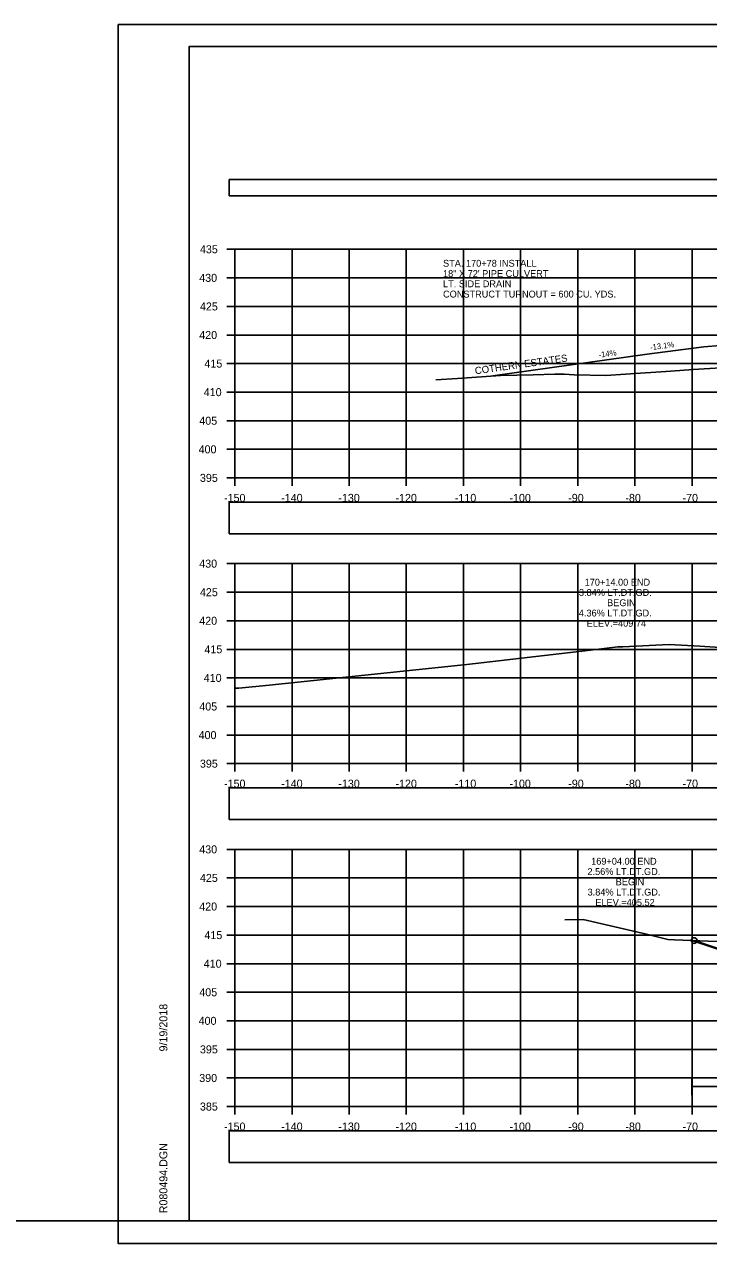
# Model space of a CAD drawing. Extents: x 1376273 to 1384221, y 378927 to 384592.
# Drawn here: x 1378403.8 to 1378523.5, y 381178.5 to 381391.9 of the extents above; entities that cross this region are included whole.
import ezdxf

# ---------------------------------------------------------------- set-up
doc = ezdxf.new("R2010")
doc.units = 0
for name, color, linetype in [('R_Axis', 7, 'Continuous'), ('R_Axis Annot', 7, 'Continuous'), ('R_Border', 7, 'Continuous'), ('R_Dimension', 7, 'Continuous'), ('R_Drive', 7, 'Continuous'), ('R_Exist Surface', 7, 'Continuous'), ('R_Fin Surface', 7, 'Continuous'), ('R_Grid', 7, 'Continuous'), ('R_No Plot', 7, 'Continuous'), ('R_Xsect Elev', 7, 'Continuous'), ('T_Detection Zones', 7, 'Continuous'), ('T_Drafting', 7, 'Continuous')]:
    doc.layers.add(name, color=color, linetype=linetype)

msp = doc.modelspace()

# ---------------------------------------------------------------- linework, layer by layer
at = {"layer": 'R_Axis'}
for p, q in [((1378439.24, 381352.51), (1378440.64, 381352.51)), ((1378440.64, 381312.51), (1378440.64, 381352.51)), ((1378439.24, 381347.51), (1378440.64, 381347.51)), ((1378439.24, 381342.51), (1378440.64, 381342.51)), ((1378439.24, 381337.51), (1378440.64, 381337.51)), ((1378439.24, 381332.51), (1378440.64, 381332.51)), ((1378439.24, 381327.51), (1378440.64, 381327.51)), ((1378439.24, 381322.51), (1378440.64, 381322.51)), ((1378439.24, 381317.51), (1378440.64, 381317.51)), ((1378439.24, 381312.51), (1378440.64, 381312.51)), ((1378440.64, 381312.51), (1378740.64, 381312.51)), ((1378440.64, 381311.11), (1378440.64, 381312.51)), ((1378450.64, 381311.11), (1378450.64, 381312.51)), ((1378460.64, 381311.11), (1378460.64, 381312.51)), ((1378470.64, 381311.11), (1378470.64, 381312.51)), ((1378480.64, 381311.11), (1378480.64, 381312.51)), ((1378490.64, 381311.11), (1378490.64, 381312.51)), ((1378500.64, 381311.11), (1378500.64, 381312.51)), ((1378510.64, 381311.11), (1378510.64, 381312.51)), ((1378520.64, 381311.11), (1378520.64, 381312.51)), ((1378439.24, 381297.51), (1378440.64, 381297.51)), ((1378440.64, 381262.51), (1378440.64, 381297.51)), ((1378439.24, 381292.51), (1378440.64, 381292.51)), ((1378439.24, 381287.51), (1378440.64, 381287.51)), ((1378439.24, 381282.51), (1378440.64, 381282.51)), ((1378439.24, 381277.51), (1378440.64, 381277.51)), ((1378439.24, 381272.51), (1378440.64, 381272.51)), ((1378439.24, 381267.51), (1378440.64, 381267.51)), ((1378439.24, 381262.51), (1378440.64, 381262.51)), ((1378440.64, 381262.51), (1378740.64, 381262.51)), ((1378440.64, 381261.11), (1378440.64, 381262.51)), ((1378450.64, 381261.11), (1378450.64, 381262.51)), ((1378460.64, 381261.11), (1378460.64, 381262.51)), ((1378470.64, 381261.11), (1378470.64, 381262.51)), ((1378480.64, 381261.11), (1378480.64, 381262.51)), ((1378490.64, 381261.11), (1378490.64, 381262.51)), ((1378500.64, 381261.11), (1378500.64, 381262.51)), ((1378510.64, 381261.11), (1378510.64, 381262.51)), ((1378520.64, 381261.11), (1378520.64, 381262.51)), ((1378439.24, 381247.51), (1378440.64, 381247.51)), ((1378440.64, 381202.51), (1378440.64, 381247.51)), ((1378439.24, 381242.51), (1378440.64, 381242.51)), ((1378439.24, 381237.51), (1378440.64, 381237.51)), ((1378439.24, 381232.51), (1378440.64, 381232.51)), ((1378439.24, 381227.51), (1378440.64, 381227.51)), ((1378439.24, 381222.51), (1378440.64, 381222.51)), ((1378439.24, 381217.51), (1378440.64, 381217.51)), ((1378439.24, 381212.51), (1378440.64, 381212.51)), ((1378439.24, 381207.51), (1378440.64, 381207.51)), ((1378439.24, 381202.51), (1378440.64, 381202.51)), ((1378440.64, 381202.51), (1378740.64, 381202.51)), ((1378440.64, 381201.11), (1378440.64, 381202.51)), ((1378450.64, 381201.11), (1378450.64, 381202.51)), ((1378460.64, 381201.11), (1378460.64, 381202.51)), ((1378470.64, 381201.11), (1378470.64, 381202.51)), ((1378480.64, 381201.11), (1378480.64, 381202.51)), ((1378490.64, 381201.11), (1378490.64, 381202.51)), ((1378500.64, 381201.11), (1378500.64, 381202.51)), ((1378510.64, 381201.11), (1378510.64, 381202.51)), ((1378520.64, 381201.11), (1378520.64, 381202.51))]:
    msp.add_line(p, q, dxfattribs=at)
at = {"layer": 'R_Axis Annot'}
for points in [[(1378439.67, 381361.89), (1378741.48, 381361.89), (1378741.48, 381364.71), (1378439.67, 381364.71)], [(1378439.67, 381302.71), (1378741.48, 381302.71), (1378741.48, 381308.24), (1378439.67, 381308.24)], [(1378439.67, 381252.75), (1378741.48, 381252.75), (1378741.48, 381258.27), (1378439.67, 381258.27)], [(1378439.67, 381192.74), (1378741.48, 381192.74), (1378741.48, 381198.26), (1378439.67, 381198.26)]]:
    msp.add_lwpolyline(points, close=True, dxfattribs=at)
at = {"layer": 'R_Border'}
for p, q in [((1378432.64, 381387.97), (1378748.82, 381387.97)), ((1378432.64, 381182.51), (1378432.64, 381387.97)), ((1378432.64, 381182.51), (1378432.64, 381182.51)), ((1378748.82, 381182.51), (1378432.64, 381182.51))]:
    msp.add_line(p, q, dxfattribs=at)
at = {"layer": 'R_Dimension'}
for p, q in [((1378520.61, 381204.52), (1378520.61, 381207.52)), ((1378520.61, 381206.02), (1378642.81, 381206.02))]:
    msp.add_line(p, q, dxfattribs=at)
at = {"layer": 'R_Drive'}
for p, q in [((1378522.7, 381335.44), (1378512.77, 381334.14)), ((1378532.66, 381336.29), (1378522.7, 381335.44)), ((1378512.77, 381334.14), (1378485.81, 381330.35))]:
    msp.add_line(p, q, dxfattribs=at)
at = {"layer": 'R_Exist Surface'}
for points in [[(1378475.81, 381329.65), (1378479.58, 381329.92), (1378487.15, 381330.44), (1378492.85, 381330.54), (1378496.66, 381330.64), (1378498.29, 381330.68), (1378499.99, 381330.56), (1378505.54, 381330.44), (1378509.01, 381330.65), (1378516.96, 381331.21), (1378520.85, 381331.49), (1378528.61, 381331.93)], [(1378440.64, 381275.69), (1378441.35, 381275.7), (1378446.67, 381276.22), (1378449.43, 381276.52), (1378481.21, 381279.83), (1378502.9, 381282.35), (1378507.67, 381282.93), (1378508.52, 381282.97), (1378516.64, 381283.36), (1378522.02, 381283.09), (1378525.57, 381282.84)], [(1378498.4, 381235.19), (1378501.62, 381235.23), (1378512.7, 381232.66), (1378516.41, 381231.73), (1378517.58, 381231.69), (1378523.49, 381231.45), (1378535.8, 381231.09)]]:
    msp.add_lwpolyline(points, dxfattribs=at)
at = {"layer": 'R_Fin Surface'}
msp.add_lwpolyline([(1378521.02, 381231.55), (1378546.9, 381222.93), (1378556.09, 381225.99), (1378556.64, 381226.17), (1378566.64, 381228.67), (1378572.64, 381228.25), (1378590.64, 381226.99), (1378608.64, 381225.74), (1378614.64, 381225.32), (1378622.04, 381223.47), (1378624.64, 381222.82), (1378630.84, 381220.75), (1378642.44, 381224.61)], dxfattribs=at)
at = {"layer": 'R_Grid'}
for p, q in [((1378440.64, 381352.51), (1378740.64, 381352.51)), ((1378440.64, 381312.51), (1378440.64, 381352.51)), ((1378450.64, 381312.51), (1378450.64, 381352.51)), ((1378460.64, 381312.51), (1378460.64, 381352.51)), ((1378470.64, 381312.51), (1378470.64, 381352.51)), ((1378480.64, 381312.51), (1378480.64, 381352.51)), ((1378490.64, 381312.51), (1378490.64, 381352.51)), ((1378500.64, 381312.51), (1378500.64, 381352.51)), ((1378510.64, 381312.51), (1378510.64, 381352.51)), ((1378520.64, 381312.51), (1378520.64, 381352.51)), ((1378440.64, 381347.51), (1378740.64, 381347.51)), ((1378440.64, 381342.51), (1378740.64, 381342.51)), ((1378440.64, 381337.51), (1378740.64, 381337.51)), ((1378440.64, 381332.51), (1378740.64, 381332.51)), ((1378440.64, 381327.51), (1378740.64, 381327.51)), ((1378440.64, 381322.51), (1378740.64, 381322.51)), ((1378440.64, 381317.51), (1378740.64, 381317.51)), ((1378440.64, 381312.51), (1378740.64, 381312.51)), ((1378440.64, 381297.51), (1378740.64, 381297.51)), ((1378440.64, 381262.51), (1378440.64, 381297.51)), ((1378450.64, 381262.51), (1378450.64, 381297.51)), ((1378460.64, 381262.51), (1378460.64, 381297.51)), ((1378470.64, 381262.51), (1378470.64, 381297.51)), ((1378480.64, 381262.51), (1378480.64, 381297.51)), ((1378490.64, 381262.51), (1378490.64, 381297.51)), ((1378500.64, 381262.51), (1378500.64, 381297.51)), ((1378510.64, 381262.51), (1378510.64, 381297.51)), ((1378520.64, 381262.51), (1378520.64, 381297.51)), ((1378440.64, 381292.51), (1378740.64, 381292.51)), ((1378440.64, 381287.51), (1378740.64, 381287.51)), ((1378440.64, 381282.51), (1378740.64, 381282.51)), ((1378440.64, 381277.51), (1378740.64, 381277.51)), ((1378440.64, 381272.51), (1378740.64, 381272.51)), ((1378440.64, 381267.51), (1378740.64, 381267.51)), ((1378440.64, 381262.51), (1378740.64, 381262.51)), ((1378440.64, 381247.51), (1378740.64, 381247.51)), ((1378440.64, 381202.51), (1378440.64, 381247.51)), ((1378450.64, 381202.51), (1378450.64, 381247.51)), ((1378460.64, 381202.51), (1378460.64, 381247.51)), ((1378470.64, 381202.51), (1378470.64, 381247.51)), ((1378480.64, 381202.51), (1378480.64, 381247.51)), ((1378490.64, 381202.51), (1378490.64, 381247.51)), ((1378500.64, 381202.51), (1378500.64, 381247.51)), ((1378510.64, 381202.51), (1378510.64, 381247.51)), ((1378520.64, 381202.51), (1378520.64, 381247.51)), ((1378440.64, 381242.51), (1378740.64, 381242.51)), ((1378440.64, 381237.51), (1378740.64, 381237.51)), ((1378440.64, 381232.51), (1378740.64, 381232.51)), ((1378440.64, 381227.51), (1378740.64, 381227.51)), ((1378440.64, 381222.51), (1378740.64, 381222.51)), ((1378440.64, 381217.51), (1378740.64, 381217.51)), ((1378440.64, 381212.51), (1378740.64, 381212.51)), ((1378440.64, 381207.51), (1378740.64, 381207.51)), ((1378440.64, 381202.51), (1378740.64, 381202.51))]:
    msp.add_line(p, q, dxfattribs=at)
at = {"layer": 'R_No Plot'}
for p, q in [((1378420.24, 381391.86), (1378753.57, 381391.86)), ((1378420.24, 381178.53), (1378753.57, 381178.53))]:
    msp.add_line(p, q, dxfattribs=at)
for points in [[(1378420.23, 381391.86), (1378753.57, 381391.86), (1378753.57, 381178.53), (1378420.23, 381178.53)], [(1378666.56, 381387.97), (1378666.56, 381378.09), (1378702.29, 381378.09), (1378702.29, 381375.17), (1378725.49, 381375.17), (1378725.49, 381350.84), (1378748.82, 381350.84), (1378748.82, 381182.51), (1378432.64, 381182.51), (1378432.64, 381387.97)]]:
    msp.add_lwpolyline(points, close=True, dxfattribs=at)
msp.add_circle((1378521.02, 381231.55), 0.5, dxfattribs=at)
at = {"layer": 'T_Detection Zones'}
msp.add_lwpolyline([(1378520.61, 381231.57), (1378523.49, 381231.45), (1378535.8, 381231.09), (1378540.35, 381230.74), (1378543.11, 381230.54), (1378545.25, 381230.54), (1378549.26, 381230.66), (1378555.96, 381229.14), (1378560.09, 381228.25), (1378561.21, 381227.87), (1378566.85, 381226.16), (1378555.55, 381225.93), (1378546.54, 381222.93), (1378545.95, 381223.12), (1378520.61, 381231.57)], close=True, dxfattribs=at)
at = {"layer": 'T_Drafting'}
msp.add_line((1378432.64, 381182.51), (1378066.46, 381182.51), dxfattribs=at)

# ---------------------------------------------------------------- texts
at = {"layer": 'R_Axis Annot'}
for s, height, p in [('435', 1.4, (1378434.53, 381351.81)), ('STA. 170+78 INSTALL', 1.2, (1378477.07, 381349.46)), ('430', 1.4, (1378434.41, 381346.81)), ('18" X 72\' PIPE CULVERT', 1.2, (1378477.07, 381347.66)), ('CONSTRUCT TURNOUT = 600 CU. YDS.', 1.2, (1378477.07, 381344.07)), ('LT. SIDE DRAIN', 1.2, (1378477.07, 381345.87)), ('425', 1.4, (1378434.53, 381341.81)), ('420', 1.4, (1378434.41, 381336.81)), ('415', 1.4, (1378435.32, 381331.81)), ('410', 1.4, (1378435.2, 381326.81)), ('405', 1.4, (1378434.42, 381321.81)), ('400', 1.4, (1378434.3, 381316.81)), ('395', 1.4, (1378434.53, 381311.81)), ('-150', 1.4, (1378438.75, 381308.31)), ('-140', 1.4, (1378448.75, 381308.31)), ('-130', 1.4, (1378458.75, 381308.31)), ('-120', 1.4, (1378468.75, 381308.31)), ('-110', 1.4, (1378479.14, 381308.31)), ('-100', 1.4, (1378488.69, 381308.31)), ('-90', 1.4, (1378498.98, 381308.31)), ('-80', 1.4, (1378508.98, 381308.31)), ('-70', 1.4, (1378518.98, 381308.31)), ('430', 1.4, (1378434.41, 381296.81)), ('425', 1.4, (1378434.53, 381291.81)), ('420', 1.4, (1378434.41, 381286.81)), ('415', 1.4, (1378435.32, 381281.81)), ('410', 1.4, (1378435.2, 381276.81)), ('405', 1.4, (1378434.42, 381271.81)), ('400', 1.4, (1378434.3, 381266.81)), ('395', 1.4, (1378434.53, 381261.81)), ('-150', 1.4, (1378438.75, 381258.31)), ('-140', 1.4, (1378448.75, 381258.31)), ('-130', 1.4, (1378458.75, 381258.31)), ('-120', 1.4, (1378468.75, 381258.31)), ('-110', 1.4, (1378479.14, 381258.31)), ('-100', 1.4, (1378488.69, 381258.31)), ('-90', 1.4, (1378498.98, 381258.31)), ('-80', 1.4, (1378508.98, 381258.31)), ('-70', 1.4, (1378518.98, 381258.31)), ('430', 1.4, (1378434.41, 381246.81)), ('425', 1.4, (1378434.53, 381241.81)), ('420', 1.4, (1378434.41, 381236.81)), ('415', 1.4, (1378435.32, 381231.81)), ('410', 1.4, (1378435.2, 381226.81)), ('405', 1.4, (1378434.42, 381221.81)), ('400', 1.4, (1378434.3, 381216.81)), ('395', 1.4, (1378434.53, 381211.81)), ('390', 1.4, (1378434.41, 381206.81)), ('385', 1.4, (1378434.53, 381201.81)), ('-150', 1.4, (1378438.75, 381198.31)), ('-140', 1.4, (1378448.75, 381198.31)), ('-130', 1.4, (1378458.75, 381198.31)), ('-120', 1.4, (1378468.75, 381198.31)), ('-110', 1.4, (1378479.14, 381198.31)), ('-100', 1.4, (1378488.69, 381198.31)), ('-90', 1.4, (1378498.98, 381198.31)), ('-80', 1.4, (1378508.98, 381198.31)), ('-70', 1.4, (1378518.98, 381198.31))]:
    msp.add_text(s, height=height, dxfattribs=at).set_placement(p)
at = {"layer": 'R_Border'}
for s, p in [('9/19/2018', (1378428.83, 381212.15)), ('R080494.DGN', (1378428.83, 381183.83))]:
    msp.add_text(s, height=1.4, rotation=90, dxfattribs=at).set_placement(p)
at = {"layer": 'R_Drive'}
for s, height, rotation, p in [('-14%', 1, 7.97, (1378504.38, 381333.52)), ('-13.1%', 1, 7.4594, (1378513.37, 381334.84)), ('COTHERN ESTATES', 1.25, 8.0186, (1378482.73, 381330.62))]:
    msp.add_text(s, height=height, rotation=rotation, dxfattribs=at).set_placement(p)
at = {"layer": 'R_Xsect Elev'}
for s, p in [('170+14.00 END', (1378501.85, 381293.66)), ('3.84% LT.DT.GD.', (1378500.85, 381291.86)), ('BEGIN', (1378505.78, 381290.06)), ('4.36% LT.DT.GD.', (1378500.83, 381288.26)), ('ELEV.=409.74', (1378502.21, 381286.46)), ('169+04.00 END', (1378502.99, 381244.83)), ('2.56% LT.DT.GD.', (1378502.34, 381243.03)), ('BEGIN', (1378507.29, 381241.23)), ('3.84% LT.DT.GD.', (1378502.36, 381239.43)), ('ELEV.=405.52', (1378503.72, 381237.63))]:
    msp.add_text(s, height=1.2, rotation=360, dxfattribs=at).set_placement(p)

doc.saveas('drawing.dxf')
